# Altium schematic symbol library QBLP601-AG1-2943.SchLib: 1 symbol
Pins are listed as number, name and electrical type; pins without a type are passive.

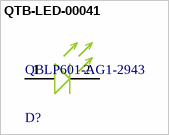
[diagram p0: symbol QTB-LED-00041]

## QTB-LED-00041
designator D?, comment QBLP601-AG1-2943
LED YELLOW/GREEN DIFFUSED 0603 SMD; Manufacturer: QT Brightek (QTB); Lens Size: 0.8mm; Luminous Intensity: 50mcd; Test Current: 20mA; Lens Color: White; Lens Style: Flat; Forward Voltage: 2.0V; Wavelength - Dominant: 570nm
footprint QBLP601-AG1-2943
pins: 1 ANODE (+), 2 CATHODE (-)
